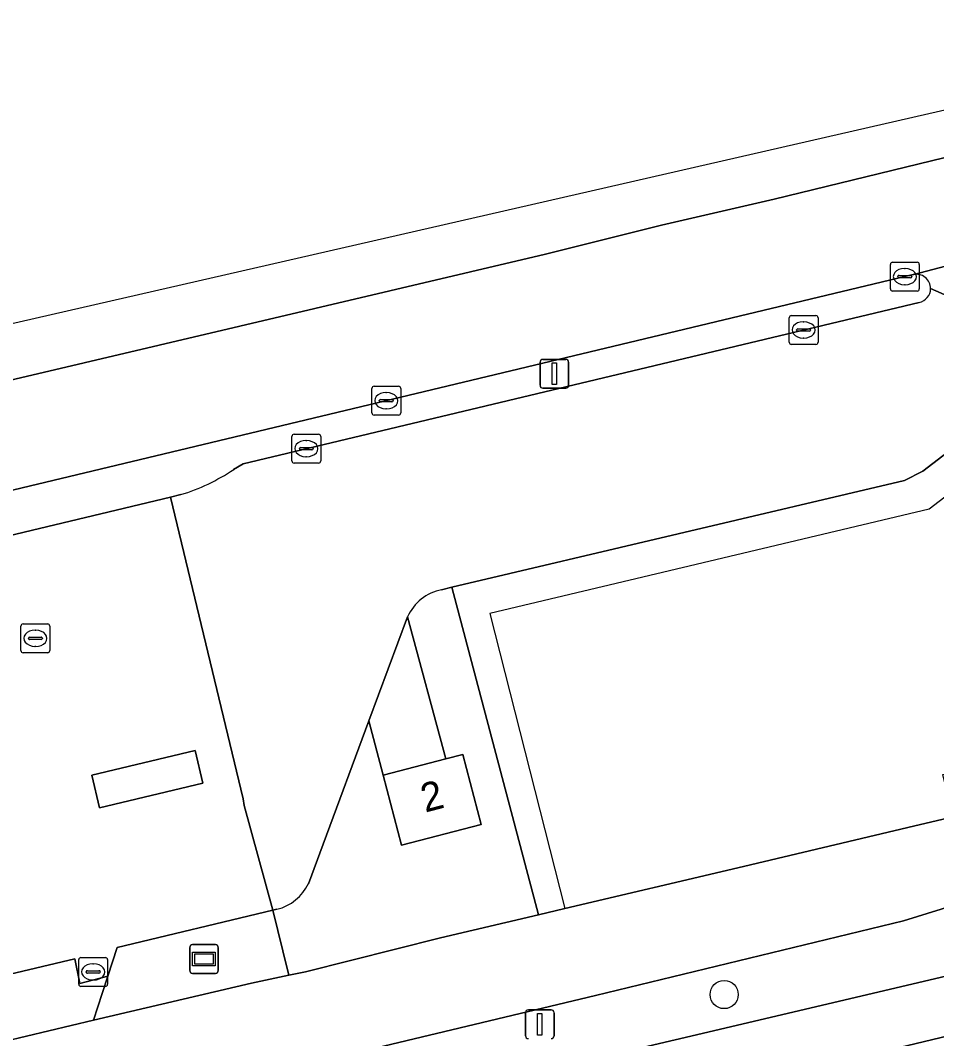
# Model space of a CAD drawing. Extents: x 157648 to 158502, y 379212 to 380938.
# Drawn here: x 158196.62 to 158228.38, y 380880.43 to 380915.73 of the extents above; entities that cross this region are included whole.
import ezdxf

# ---------------------------------------------------------------- set-up
doc = ezdxf.new("R2010")
doc.units = 0
for name, color, linetype in [('IMGEO_Berm_groen', 7, 'Continuous'), ('IMGEO_Boom', 7, 'Continuous'), ('IMGEO_Erf', 7, 'Continuous'), ('IMGEO_Fietspad_gesloten', 7, 'Continuous'), ('IMGEO_Groenvoorziening', 7, 'Continuous'), ('IMGEO_Hek', 7, 'Continuous'), ('IMGEO_Informatiebord', 7, 'Continuous'), ('IMGEO_Kolk', 7, 'Continuous'), ('IMGEO_Lichtmast', 7, 'Continuous'), ('IMGEO_Pand', 7, 'Continuous'), ('IMGEO_Pand_nummerreeks', 7, 'Continuous'), ('IMGEO_Rijbaan_lokaal_gesloten', 7, 'Continuous'), ('IMGEO_Rijbaan_lokaal_open', 7, 'Continuous'), ('IMGEO_Rijbaan_regionaal_gesloten', 7, 'Continuous'), ('IMGEO_Verkeerseiland_gesloten', 7, 'Continuous'), ('IMGEO_Verkeerseiland_open', 7, 'Continuous'), ('IMGEO_Voetpad_halfverhard', 7, 'Continuous'), ('IMGEO_Voetpad_open', 7, 'Continuous')]:
    doc.layers.add(name, color=color, linetype=linetype)

msp = doc.modelspace()

# ---------------------------------------------------------------- linework, layer by layer
at = {"layer": 'IMGEO_Berm_groen'}
for points in [[(158247.927, 380894.961), (158241.25, 380890.308), (158241.053, 380890.179), (158237.983, 380888.371), (158234.764, 380886.844), (158227.239, 380884.51), (158216.562, 380881.917), (158176.169, 380872.274), (158170.786, 380871.038), (158169.397, 380870.904), (158167.571, 380870.872), (158165.75, 380871.003), (158163.948, 380871.297), (158155.69, 380872.659), (158150.365, 380873.521), (158148.523, 380873.783), (158145.729, 380873.832), (158142.943, 380873.632), (158141.381, 380873.409), (158125.611, 380869.701), (158120.899, 380868.795), (158112.29, 380866.807), (158104.631, 380865.308)], [(158175.796, 380870.028), (158198.003, 380875.375), (158230.074, 380882.921), (158233.565, 380883.858), (158235.501, 380884.527), (158238.669, 380885.752), (158241.715, 380887.254), (158242.343, 380887.608), (158251.028, 380892.001)]]:
    msp.add_lwpolyline(points, dxfattribs=at)
at = {"layer": 'IMGEO_Boom'}
msp.add_circle((158221.018, 380881.956), 0.489, dxfattribs=at)
at = {"layer": 'IMGEO_Erf'}
msp.add_lwpolyline([(158233.252, 380904.195), (158227.91, 380900.104), (158227.265, 380899.78), (158211.577, 380896.08), (158214.584, 380884.721), (158215.49, 380884.935), (158221.487, 380886.347), (158227.823, 380887.854), (158228.952, 380888.114), (158228.593, 380889.586), (158233.102, 380890.692), (158238.4, 380893.573)], dxfattribs=at)
at = {"layer": 'IMGEO_Fietspad_gesloten'}
for points in [[(158104.631, 380865.308), (158112.29, 380866.807), (158120.899, 380868.795), (158125.611, 380869.701), (158141.381, 380873.409), (158142.943, 380873.632), (158145.729, 380873.832), (158148.523, 380873.783), (158150.365, 380873.521), (158155.69, 380872.659), (158163.948, 380871.297), (158165.75, 380871.003), (158167.571, 380870.872), (158169.397, 380870.904), (158170.786, 380871.038), (158176.169, 380872.274), (158216.562, 380881.917), (158227.239, 380884.51), (158234.764, 380886.844), (158237.983, 380888.371), (158241.053, 380890.179), (158241.25, 380890.308), (158247.927, 380894.961)], [(158228.952, 380888.114), (158227.823, 380887.854), (158221.487, 380886.347), (158215.49, 380884.935), (158214.584, 380884.721), (158211.181, 380883.92), (158206.509, 380882.744), (158205.929, 380882.622), (158204.633, 380882.349), (158199.155, 380881.064), (158186.759, 380878.107), (158172.2, 380874.603), (158169.254, 380874.341), (158166.261, 380874.42), (158160.22, 380875.155), (158152.042, 380876.575), (158149.385, 380877.016), (158147.961, 380877.094)]]:
    msp.add_lwpolyline(points, dxfattribs=at)
at = {"layer": 'IMGEO_Groenvoorziening'}
msp.add_lwpolyline([(158253.447, 380890.878), (158244.278, 380886.139), (158242.731, 380885.244), (158240.021, 380883.923), (158237.204, 380882.85), (158231.096, 380881.082), (158178.582, 380868.481), (158173.991, 380867.557), (158171.184, 380867.259), (158167.176, 380867), (158165.172, 380867.015)], dxfattribs=at)
at = {"layer": 'IMGEO_Hek'}
for points in [[(158236.116, 380904.381), (158234.153, 380903.401), (158228.121, 380898.781), (158212.895, 380895.165), (158215.49, 380884.935)], [(158204.633, 380882.349), (158199.155, 380881.064)], [(158199.155, 380881.064), (158186.759, 380878.107)]]:
    msp.add_lwpolyline(points, dxfattribs=at)
at = {"layer": 'IMGEO_Informatiebord'}
for p, q in [((158202.59, 380883.688), (158203.38, 380883.688)), ((158203.38, 380883.688), (158202.59, 380883.688)), ((158202.49, 380882.788), (158202.49, 380883.588)), ((158202.49, 380883.588), (158202.49, 380882.788)), ((158203.48, 380883.588), (158203.48, 380882.788)), ((158203.48, 380882.788), (158203.48, 380883.588)), ((158203.38, 380882.688), (158202.59, 380882.688)), ((158202.59, 380882.688), (158203.38, 380882.688))]:
    msp.add_line(p, q, dxfattribs=at)
for points in [[(158202.591, 380883.42), (158203.379, 380883.42), (158203.379, 380882.956), (158202.591, 380882.956), (158202.591, 380883.42)], [(158202.656, 380883.355), (158202.656, 380883.021), (158203.314, 380883.021), (158203.314, 380883.355), (158202.656, 380883.355)]]:
    msp.add_lwpolyline(points, dxfattribs=at)
for centre, start, end in [((158202.59, 380883.588), 90, 180), ((158202.59, 380883.588), 90, 180), ((158203.38, 380883.588), 0, 90), ((158203.38, 380883.588), 360, 90), ((158202.59, 380882.788), 180, 270), ((158202.59, 380882.788), 180, 270), ((158203.38, 380882.788), 270, 0), ((158203.38, 380882.788), 270, 0)]:
    msp.add_arc(centre, 0.1, start, end, dxfattribs=at)
at = {"layer": 'IMGEO_Kolk'}
for p, q in [((158226.857, 380907.342), (158227.709, 380907.342)), ((158226.782, 380906.416), (158226.782, 380907.268)), ((158227.27, 380907.122), (158227.295, 380907.122)), ((158227.783, 380907.268), (158227.783, 380906.416)), ((158227.041, 380906.836), (158227.041, 380906.848)), ((158227.479, 380906.799), (158227.081, 380906.799)), ((158227.084, 380906.885), (158227.482, 380906.885)), ((158227.525, 380906.848), (158227.525, 380906.836)), ((158227.709, 380906.342), (158226.857, 380906.342)), ((158227.293, 380906.562), (158227.268, 380906.562)), ((158223.271, 380904.567), (158223.271, 380905.419)), ((158223.346, 380905.493), (158224.198, 380905.493)), ((158223.759, 380905.273), (158223.784, 380905.273)), ((158224.272, 380905.419), (158224.272, 380904.567)), ((158223.53, 380904.987), (158223.53, 380904.999)), ((158223.968, 380904.95), (158223.57, 380904.95)), ((158223.573, 380905.036), (158223.971, 380905.036)), ((158224.014, 380904.999), (158224.014, 380904.987)), ((158224.198, 380904.493), (158223.346, 380904.493)), ((158223.782, 380904.713), (158223.757, 380904.713)), ((158208.805, 380902.116), (158208.805, 380902.968)), ((158208.88, 380903.042), (158209.732, 380903.042)), ((158209.293, 380902.822), (158209.318, 380902.822)), ((158209.806, 380902.968), (158209.806, 380902.116)), ((158209.064, 380902.536), (158209.064, 380902.548)), ((158209.502, 380902.499), (158209.104, 380902.499)), ((158209.107, 380902.585), (158209.505, 380902.585)), ((158209.548, 380902.548), (158209.548, 380902.536)), ((158209.732, 380902.042), (158208.88, 380902.042)), ((158209.316, 380902.262), (158209.291, 380902.262)), ((158206.033, 380900.453), (158206.033, 380901.305)), ((158206.108, 380901.379), (158206.96, 380901.379)), ((158207.034, 380901.305), (158207.034, 380900.453)), ((158206.521, 380901.159), (158206.546, 380901.159)), ((158206.292, 380900.873), (158206.292, 380900.885)), ((158206.73, 380900.836), (158206.332, 380900.836)), ((158206.335, 380900.922), (158206.733, 380900.922)), ((158206.544, 380900.599), (158206.519, 380900.599)), ((158206.776, 380900.885), (158206.776, 380900.873)), ((158206.96, 380900.379), (158206.108, 380900.379)), ((158196.641, 380893.878), (158196.641, 380894.73)), ((158196.716, 380894.804), (158197.568, 380894.804)), ((158197.642, 380894.73), (158197.642, 380893.878)), ((158196.9, 380894.298), (158196.9, 380894.31)), ((158197.338, 380894.261), (158196.94, 380894.261)), ((158196.943, 380894.347), (158197.341, 380894.347)), ((158197.129, 380894.584), (158197.154, 380894.584)), ((158197.384, 380894.31), (158197.384, 380894.298)), ((158197.152, 380894.024), (158197.127, 380894.024)), ((158197.568, 380893.804), (158196.716, 380893.804)), ((158198.644, 380882.314), (158198.644, 380883.166)), ((158198.719, 380883.24), (158199.571, 380883.24)), ((158199.132, 380883.02), (158199.157, 380883.02)), ((158199.645, 380883.166), (158199.645, 380882.314)), ((158198.903, 380882.734), (158198.903, 380882.746)), ((158199.341, 380882.697), (158198.943, 380882.697)), ((158198.946, 380882.783), (158199.344, 380882.783)), ((158199.387, 380882.746), (158199.387, 380882.734)), ((158199.571, 380882.24), (158198.719, 380882.24)), ((158199.155, 380882.46), (158199.13, 380882.46))]:
    msp.add_line(p, q, dxfattribs=at)
for points in [[(158226.857, 380907.342), (158227.709, 380907.342)], [(158226.782, 380906.416), (158226.782, 380907.268)], [(158227.783, 380907.268), (158227.783, 380906.416)], [(158227.709, 380906.342), (158226.857, 380906.342)], [(158223.271, 380904.567), (158223.271, 380905.419)], [(158223.346, 380905.493), (158224.198, 380905.493)], [(158224.272, 380905.419), (158224.272, 380904.567)], [(158224.198, 380904.493), (158223.346, 380904.493)], [(158208.805, 380902.116), (158208.805, 380902.968)], [(158208.88, 380903.042), (158209.732, 380903.042)], [(158209.806, 380902.968), (158209.806, 380902.116)], [(158209.732, 380902.042), (158208.88, 380902.042)], [(158206.033, 380900.453), (158206.033, 380901.305)], [(158206.108, 380901.379), (158206.96, 380901.379)], [(158207.034, 380901.305), (158207.034, 380900.453)], [(158206.96, 380900.379), (158206.108, 380900.379)], [(158196.641, 380893.878), (158196.641, 380894.73)], [(158196.716, 380894.804), (158197.568, 380894.804)], [(158197.642, 380894.73), (158197.642, 380893.878)], [(158197.568, 380893.804), (158196.716, 380893.804)], [(158198.644, 380882.314), (158198.644, 380883.166)], [(158198.719, 380883.24), (158199.571, 380883.24)], [(158199.645, 380883.166), (158199.645, 380882.314)], [(158199.571, 380882.24), (158198.719, 380882.24)]]:
    msp.add_lwpolyline(points, dxfattribs=at)
for centre, radius, start, end in [((158226.859, 380907.266), 0.0765, 91.552, 178.448), ((158226.859, 380907.266), 0.0765, 91.552, 178.448), ((158227.707, 380907.266), 0.0765, 1.552, 88.448), ((158227.707, 380907.266), 0.0765, 1.552, 88.448), ((158227.081, 380906.845), 0.0403, 85.8775, 175.7526), ((158227.078, 380906.835), 0.0366, 178.938, 274.7102), ((158227.482, 380906.842), 0.043, 264.8664, 352.4533), ((158227.486, 380906.847), 0.0386, 1.7309, 96.639), ((158226.859, 380906.418), 0.0765, 181.552, 268.448), ((158226.859, 380906.418), 0.0765, 181.552, 268.448), ((158227.707, 380906.418), 0.0765, 271.552, 358.448), ((158227.707, 380906.418), 0.0765, 271.552, 358.448), ((158223.348, 380905.417), 0.0765, 91.552, 178.448), ((158223.348, 380905.417), 0.0765, 91.552, 178.448), ((158224.196, 380905.417), 0.0765, 1.552, 88.448), ((158224.196, 380905.417), 0.0765, 1.552, 88.448), ((158223.57, 380904.996), 0.0403, 85.8775, 175.7526), ((158223.567, 380904.986), 0.0366, 178.938, 274.7102), ((158223.971, 380904.993), 0.043, 264.8664, 352.4533), ((158223.975, 380904.998), 0.0386, 1.7309, 96.639), ((158223.348, 380904.569), 0.0765, 181.552, 268.448), ((158223.348, 380904.569), 0.0765, 181.552, 268.448), ((158224.196, 380904.569), 0.0765, 271.552, 358.448), ((158224.196, 380904.569), 0.0765, 271.552, 358.448), ((158208.882, 380902.966), 0.0765, 91.552, 178.448), ((158208.882, 380902.966), 0.0765, 91.552, 178.448), ((158209.73, 380902.966), 0.0765, 1.552, 88.448), ((158209.73, 380902.966), 0.0765, 1.552, 88.448), ((158209.104, 380902.545), 0.0403, 85.8775, 175.7526), ((158209.101, 380902.535), 0.0366, 178.938, 274.7102), ((158209.505, 380902.542), 0.043, 264.8664, 352.4533), ((158209.509, 380902.547), 0.0386, 1.7309, 96.639), ((158208.882, 380902.118), 0.0765, 181.552, 268.448), ((158208.882, 380902.118), 0.0765, 181.552, 268.448), ((158209.73, 380902.118), 0.0765, 271.552, 358.448), ((158209.73, 380902.118), 0.0765, 271.552, 358.448), ((158206.11, 380901.303), 0.0765, 91.552, 178.448), ((158206.11, 380901.303), 0.0765, 91.552, 178.448), ((158206.958, 380901.303), 0.0765, 1.552, 88.448), ((158206.958, 380901.303), 0.0765, 1.552, 88.448), ((158206.332, 380900.882), 0.0403, 85.8775, 175.7526), ((158206.329, 380900.872), 0.0366, 178.938, 274.7102), ((158206.733, 380900.879), 0.043, 264.8664, 352.4533), ((158206.737, 380900.884), 0.0386, 1.7309, 96.639), ((158206.11, 380900.455), 0.0765, 181.552, 268.448), ((158206.11, 380900.455), 0.0765, 181.552, 268.448), ((158206.958, 380900.455), 0.0765, 271.552, 358.448), ((158206.958, 380900.455), 0.0765, 271.552, 358.448), ((158196.718, 380894.728), 0.0765, 91.552, 178.448), ((158196.718, 380894.728), 0.0765, 91.552, 178.448), ((158197.566, 380894.728), 0.0765, 1.552, 88.448), ((158197.566, 380894.728), 0.0765, 1.552, 88.448), ((158196.94, 380894.307), 0.0403, 85.8775, 175.7526), ((158196.937, 380894.297), 0.0366, 178.938, 274.7102), ((158197.341, 380894.304), 0.043, 264.8664, 352.4533), ((158197.345, 380894.309), 0.0386, 1.7309, 96.639), ((158196.718, 380893.88), 0.0765, 181.552, 268.448), ((158196.718, 380893.88), 0.0765, 181.552, 268.448), ((158197.566, 380893.88), 0.0765, 271.552, 358.448), ((158197.566, 380893.88), 0.0765, 271.552, 358.448), ((158198.721, 380883.164), 0.0765, 91.552, 178.448), ((158198.721, 380883.164), 0.0765, 91.552, 178.448), ((158199.569, 380883.164), 0.0765, 1.552, 88.448), ((158199.569, 380883.164), 0.0765, 1.552, 88.448), ((158198.943, 380882.743), 0.0403, 85.8775, 175.7526), ((158198.94, 380882.733), 0.0366, 178.938, 274.7102), ((158199.344, 380882.74), 0.043, 264.8664, 352.4533), ((158199.348, 380882.745), 0.0386, 1.7309, 96.639), ((158198.721, 380882.316), 0.0765, 181.552, 268.448), ((158198.721, 380882.316), 0.0765, 181.552, 268.448), ((158199.569, 380882.316), 0.0765, 271.552, 358.448), ((158199.569, 380882.316), 0.0765, 271.552, 358.448)]:
    msp.add_arc(centre, radius, start, end, dxfattribs=at)
for centre, major_axis, ratio, start_param, end_param in [((158227.269, 380906.842), (-0.387, 0.002), 0.722429, 4.712389, 7.853982), ((158227.294, 380906.842), (-0.39, 0.002), 0.717154, 1.570796, 4.712389), ((158223.758, 380904.993), (-0.387, 0.002), 0.722429, 4.712389, 7.853982), ((158223.783, 380904.993), (-0.39, 0.002), 0.717154, 1.570796, 4.712389), ((158209.292, 380902.542), (-0.387, 0.002), 0.722429, 4.712389, 7.853982), ((158209.317, 380902.542), (-0.39, 0.002), 0.717154, 1.570796, 4.712389), ((158206.52, 380900.879), (-0.387, 0.002), 0.722429, 4.712389, 7.853982), ((158206.545, 380900.879), (-0.39, 0.002), 0.717154, 1.570796, 4.712389), ((158197.128, 380894.304), (-0.387, 0.002), 0.722429, 4.712389, 7.853982), ((158197.153, 380894.304), (-0.39, 0.002), 0.717154, 1.570796, 4.712389), ((158199.131, 380882.74), (-0.387, 0.002), 0.722429, 4.712389, 7.853982), ((158199.156, 380882.74), (-0.39, 0.002), 0.717154, 1.570796, 4.712389)]:
    msp.add_ellipse(centre, major_axis=major_axis, ratio=ratio, start_param=start_param, end_param=end_param, dxfattribs=at)
at = {"layer": 'IMGEO_Lichtmast'}
for p, q in [((158214.637, 380903.074), (158214.637, 380903.874)), ((158214.637, 380903.874), (158214.637, 380903.074)), ((158214.737, 380903.974), (158215.527, 380903.974)), ((158215.527, 380903.974), (158214.737, 380903.974)), ((158215.627, 380903.874), (158215.627, 380903.074)), ((158215.627, 380903.074), (158215.627, 380903.874)), ((158215.527, 380902.974), (158214.737, 380902.974)), ((158214.737, 380902.974), (158215.527, 380902.974)), ((158214.131, 380880.527), (158214.131, 380881.327)), ((158214.131, 380881.327), (158214.131, 380880.527)), ((158214.231, 380881.427), (158215.021, 380881.427)), ((158215.021, 380881.427), (158214.231, 380881.427)), ((158215.121, 380881.327), (158215.121, 380880.527)), ((158215.121, 380880.527), (158215.121, 380881.327))]:
    msp.add_line(p, q, dxfattribs=at)
for points in [[(158215.057, 380903.849), (158215.207, 380903.849), (158215.207, 380903.099), (158215.057, 380903.099), (158215.057, 380903.849)], [(158214.551, 380881.302), (158214.701, 380881.302), (158214.701, 380880.552), (158214.551, 380880.552), (158214.551, 380881.302)]]:
    msp.add_lwpolyline(points, dxfattribs=at)
for centre, start, end in [((158214.737, 380903.874), 90, 180), ((158214.737, 380903.874), 90, 180), ((158215.527, 380903.874), 0, 90), ((158215.527, 380903.874), 360, 90), ((158214.737, 380903.074), 180, 270), ((158214.737, 380903.074), 180, 270), ((158215.527, 380903.074), 270, 0), ((158215.527, 380903.074), 270, 0), ((158214.231, 380881.327), 90, 180), ((158214.231, 380881.327), 90, 180), ((158215.021, 380881.327), 0, 90), ((158215.021, 380881.327), 360, 90), ((158214.231, 380880.527), 180, 270), ((158214.231, 380880.527), 180, 270), ((158215.021, 380880.527), 270, 0), ((158215.021, 380880.527), 270, 0)]:
    msp.add_arc(centre, 0.1, start, end, dxfattribs=at)
at = {"layer": 'IMGEO_Pand'}
msp.add_lwpolyline([(158209.837, 380887.13), (158212.594, 380887.85), (158211.959, 380890.28), (158211.367, 380890.125), (158209.202, 380889.559)], close=True, dxfattribs=at)
at = {"layer": 'IMGEO_Rijbaan_lokaal_gesloten'}
for points in [[(158201.827, 380899.202), (158188.963, 380896.127), (158185.622, 380895.329), (158189.039, 380880.951), (158192.403, 380881.745), (158198.513, 380883.189), (158198.683, 380882.333), (158199.653, 380882.597), (158199.974, 380883.586), (158205.367, 380884.878), (158204.377, 380888.514), (158204.341, 380888.738)], [(158202.675, 380890.413), (158202.946, 380889.285), (158199.367, 380888.427), (158199.097, 380889.556)]]:
    msp.add_lwpolyline(points, close=True, dxfattribs=at)
at = {"layer": 'IMGEO_Rijbaan_lokaal_open'}
for points in [[(158211.221, 380895.986), (158211.577, 380896.08), (158227.265, 380899.78), (158227.91, 380900.104), (158233.252, 380904.195), (158228.174, 380906.425)], [(158227.779, 380905.95), (158204.341, 380900.357), (158204.015, 380900.159)], [(158202.18, 380899.286), (158201.827, 380899.202), (158204.341, 380888.738), (158204.377, 380888.514), (158205.367, 380884.878), (158205.516, 380884.914)], [(158206.606, 380885.799), (158207.116, 380887.172), (158208.702, 380891.44), (158210.044, 380895.05)]]:
    msp.add_lwpolyline(points, dxfattribs=at)
for centre, radius, start, end in [((158227.683, 380906.431), 0.491, 281.2455, 359.2621), ((158200.224, 380905.763), 6.766, 286.8062, 304.0792), ((158211.524, 380894.397), 1.618, 100.7935, 156.1929), ((158205.134, 380886.499), 1.63, 283.565, 334.5832)]:
    msp.add_arc(centre, radius, start, end, dxfattribs=at)
at = {"layer": 'IMGEO_Rijbaan_regionaal_gesloten'}
for points in [[(158322.666, 380934.145), (158125.833, 380889.066), (158052.871, 380883.253)], [(158301.101, 380921.543), (158305.33, 380922.573), (158324.416, 380927.109), (158323.73, 380929.867), (158312.504, 380927.227), (158305.087, 380925.483), (158295.501, 380923.229), (158285.916, 380920.974), (158276.489, 380918.656), (158264.922, 380915.897), (158257.255, 380914.069), (158245.832, 380911.345), (158234.792, 380908.812), (158227.589, 380906.916), (158227.57, 380906.91)], [(158246.458, 380915.211), (158244.539, 380914.756), (158238.668, 380913.364), (158234.632, 380912.366), (158230.487, 380911.415), (158222.755, 380909.522), (158218.848, 380908.629), (158214.827, 380907.623), (158206.828, 380905.74), (158190.824, 380901.973)], [(158190.824, 380901.973), (158206.828, 380905.74), (158214.827, 380907.623), (158218.848, 380908.629), (158222.755, 380909.522), (158230.487, 380911.415), (158234.632, 380912.366), (158238.668, 380913.364), (158244.539, 380914.756), (158246.458, 380915.211)], [(158108.098, 380883.225), (158111.93, 380883.562), (158115.871, 380883.958), (158119.805, 380884.419), (158121.91, 380884.621), (158125.792, 380885.125), (158129.602, 380885.619), (158139.469, 380887.076), (158145.241, 380887.993), (158149.175, 380888.767), (158157.971, 380890.35), (158178.311, 380895.13), (158178.332, 380895.132), (158227.57, 380906.91), (158227.589, 380906.916), (158234.792, 380908.812), (158245.832, 380911.345), (158257.255, 380914.069)], [(158228.174, 380906.425), (158233.252, 380904.195)]]:
    msp.add_lwpolyline(points, dxfattribs=at)
msp.add_arc((158227.683, 380906.432), 0.492, 359.2392, 103.2332, dxfattribs=at)
at = {"layer": 'IMGEO_Verkeerseiland_gesloten'}
msp.add_lwpolyline([(158202.946, 380889.285), (158202.675, 380890.413), (158199.097, 380889.556), (158199.367, 380888.427)], close=True, dxfattribs=at)
at = {"layer": 'IMGEO_Verkeerseiland_open'}
for points in [[(158227.57, 380906.91), (158178.332, 380895.132)], [(158204.015, 380900.159), (158204.341, 380900.357), (158227.779, 380905.95)], [(158188.963, 380896.127), (158201.827, 380899.202), (158202.18, 380899.286)]]:
    msp.add_lwpolyline(points, dxfattribs=at)
for centre, radius, start, end in [((158227.683, 380906.432), 0.492, 359.2392, 103.2332), ((158227.683, 380906.431), 0.491, 281.2455, 359.2621), ((158200.224, 380905.763), 6.766, 286.8062, 304.0792)]:
    msp.add_arc(centre, radius, start, end, dxfattribs=at)
at = {"layer": 'IMGEO_Voetpad_halfverhard'}
for points in [[(158205.516, 380884.914), (158205.367, 380884.878), (158205.717, 380883.473), (158205.929, 380882.622), (158206.509, 380882.744), (158211.181, 380883.92), (158214.584, 380884.721), (158211.577, 380896.08)], [(158211.577, 380896.08), (158211.221, 380895.986)], [(158210.044, 380895.05), (158211.367, 380890.125), (158211.959, 380890.28), (158212.594, 380887.85), (158209.837, 380887.13), (158209.202, 380889.559), (158208.702, 380891.44), (158207.116, 380887.172), (158206.606, 380885.799)], [(158199.456, 380881.991), (158199.653, 380882.597), (158198.683, 380882.333), (158198.513, 380883.189), (158192.403, 380881.745), (158189.039, 380880.951), (158188.815, 380880.898)], [(158187.188, 380879.441), (158186.574, 380879.312), (158186.759, 380878.107), (158199.155, 380881.064), (158199.456, 380881.991)]]:
    msp.add_lwpolyline(points, dxfattribs=at)
for centre, radius, start, end in [((158211.524, 380894.397), 1.618, 100.7935, 156.1929), ((158205.134, 380886.499), 1.63, 283.565, 334.5832)]:
    msp.add_arc(centre, radius, start, end, dxfattribs=at)
at = {"layer": 'IMGEO_Voetpad_open'}
for points in [[(158211.367, 380890.125), (158210.044, 380895.05), (158208.702, 380891.44), (158209.202, 380889.559)], [(158199.155, 380881.064), (158204.633, 380882.349), (158205.929, 380882.622), (158205.717, 380883.473), (158205.367, 380884.878), (158199.974, 380883.586), (158199.653, 380882.597), (158199.456, 380881.991)]]:
    msp.add_lwpolyline(points, close=True, dxfattribs=at)
msp.add_lwpolyline([(158251.028, 380892.001), (158242.343, 380887.608), (158241.715, 380887.254), (158238.669, 380885.752), (158235.501, 380884.527), (158233.565, 380883.858), (158230.074, 380882.921), (158198.003, 380875.375), (158175.796, 380870.028), (158175.184, 380869.895), (158171.914, 380869.367), (158168.609, 380869.132), (158165.296, 380869.194), (158165.172, 380867.015), (158167.176, 380867), (158171.184, 380867.259), (158173.991, 380867.557), (158178.582, 380868.481), (158231.096, 380881.082)], dxfattribs=at)

# ---------------------------------------------------------------- texts
at = {"layer": 'IMGEO_Pand_nummerreeks'}
msp.add_text('2', height=1, rotation=14.642, dxfattribs=at).set_placement((158210.651, 380888.259))

doc.saveas('drawing.dxf')
